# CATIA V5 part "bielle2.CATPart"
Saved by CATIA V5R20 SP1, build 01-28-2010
Part number: bielle2
Bounding box of the stored display mesh (mm): x -96.737 to -18.101, y 0 to 5, z 98 to 112
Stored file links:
  E:\EDELI\gcausse\Edeli_2012_233_gcausse\bielle2.CATPart
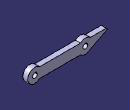
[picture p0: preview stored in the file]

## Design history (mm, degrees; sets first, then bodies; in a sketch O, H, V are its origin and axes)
Body1 (main body)
  Sketch1 on zx-plane, origin (0, 0, 0), H (-1, 0, 0), V (0, 0, 1)
    line L1 (70.202, 110) -> (30, 110)
    line L2 (70.202, 100) -> (30, 100)
    arc A1 centre (75.101, 105) radius 7 from (70.202, 110) to (70.202, 100) cw
    point P5 (75.101, 105)
    arc A2 centre (25.101, 105) radius 7 from (30, 110) to (30, 100) ccw
    point P6 (25.101, 105)
    circle A3 centre (25.101, 105) radius 2.5
    circle A4 centre (75.101, 105) radius 2.5
    radius A2 = 7
    radius A1 = 7
    distance L1 L2 = 10
    distance P6 L1 = 5
    distance P5 L2 = 5
    radius A4 = 2.5
    radius A3 = 2.5
    distance P5 P6 = 50
    horizontal: L1 H, L2 H
  Pad1: profile Sketch1, direction (0, 1, 0), length 5
  Sketch2 on end face of Pad1, origin (0, 5, 0), H (-1, 0, 0), V (0, 0, 1)
    line L1 (80, 110) -> (100, 110)
    line L2 (100, 110) -> (80, 100)
    line L3 (80, 110) -> (80, 100)
    horizontal: L1 H
    vertical: L3 V
  Pad2: profile Sketch2, direction (0, -1, 0), length 5
  Fillet1: radius 1, on edge [face of Pad2 from Sketch2.L2 | face of Pad2 from Sketch2.L1]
